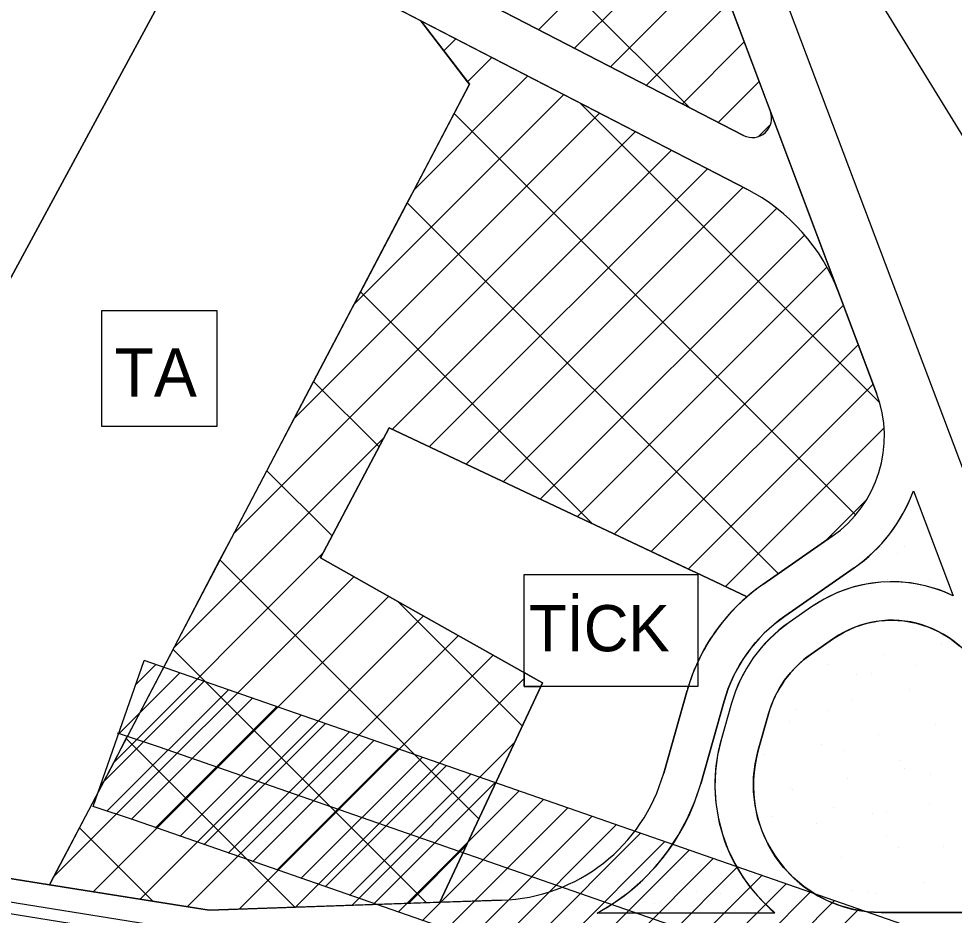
# Model space of a CAD drawing. Extents: x 409341 to 428634, y 4447481 to 4463281.
# Drawn here: x 419431.2 to 419674.1, y 4460066.6 to 4460299.4 of the extents above; entities that cross this region are included whole.
import ezdxf

# ---------------------------------------------------------------- set-up
doc = ezdxf.new("R2010")
doc.units = 0
for name, color, linetype in [('ADA', 7, 'Continuous'), ('ADAKENARI', 7, 'Continuous'), ('Default', 7, 'Continuous'), ('KALDIRIM', 7, 'Continuous'), ('LJ_SEMBOL', 7, 'Continuous'), ('OSB', 7, 'Continuous'), ('PL_AYA_PARK_DINLENME', 7, 'Continuous'), ('PL_K_DEPOLAMA', 7, 'Continuous'), ('PL_K_K_D_K_C_A', 7, 'Continuous'), ('PL_TA_K_TA', 7, 'Continuous'), ('PL_TİCK', 7, 'Continuous'), ('TA_ENH', 7, 'Continuous'), ('TA_ENH_KORUMA', 7, 'Continuous'), ('TA_ENH_TARAMA', 7, 'Continuous'), ('TR_KONUTDISIKCA', 7, 'Continuous'), ('TR_PARKALANI', 7, 'Continuous'), ('TR_TALIISMERK', 7, 'Continuous'), ('TR_TARIM_HAYVANCILIK', 7, 'Continuous'), ('TR_TİCK', 7, 'Continuous')]:
    doc.layers.add(name, color=color, linetype=linetype)

# ---------------------------------------------------------------- blocks, each defined once
blk = doc.blocks.new('POINT_DISPLAY')
at = {"layer": 'Default'}
blk.add_line((0, 0), (0, 0), dxfattribs=at)

msp = doc.modelspace()

# ---------------------------------------------------------------- linework, layer by layer
at = {"layer": 'ADA'}
for p, q in [((419535.64, 4460298.88), (419548.24, 4460282.39)), ((419548.24, 4460282.39), (419439.26, 4460074.5))]:
    msp.add_line(p, q, dxfattribs=at)
at = {"layer": 'ADAKENARI'}
for p, q in [((419536.94, 4460512.57), (419653.98, 4460202.18)), ((419653.98, 4460202.18), (419625.1, 4460278.77)), ((419663.53, 4460176.84), (419673.82, 4460149.56)), ((419642.43, 4460165), (419624.4, 4460152.46)), ((419648.14, 4460156.79), (419630.11, 4460144.25)), ((419637.11, 4460146.68), (419631.25, 4460142.61)), ((419642.82, 4460138.47), (419636.96, 4460134.4)), ((419604.76, 4460124.92), (419598.7, 4460103.49)), ((419614.38, 4460122.19), (419608.32, 4460100.77)), ((419616.31, 4460121.65), (419613.62, 4460112.17)), ((419625.93, 4460118.92), (419623.25, 4460109.45)), ((419439.26, 4460074.5), (419344.65, 4460089.57)), ((419480.72, 4460067.89), (419439.26, 4460074.5)), ((419556.61, 4460070.51), (419480.72, 4460067.89)), ((419581.44, 4460067.18), (419627.56, 4460067.26)), ((419655.17, 4460067.31), (419821.17, 4460067.62))]:
    msp.add_line(p, q, dxfattribs=at)
for points in [[(419475.21, 4460317.39), (419379.85, 4460141.06), (419371.61, 4460146.37), (419358.33, 4460118.38)], [(419476.15, 4460316.98), (419525.99, 4460303.86), (419620.27, 4460255.16)], [(419619.43, 4460269.09), (419530.32, 4460315.13)], [(419619.43, 4460269.09), (419530.32, 4460315.13)], [(419620.34, 4460149.32), (419585.57, 4460165.71), (419553.68, 4460180.75), (419527.39, 4460193.14), (419521.9, 4460182.73), (419509.56, 4460159.37), (419534.24, 4460145.49), (419567.26, 4460126.91), (419540.58, 4460069.96)]]:
    msp.add_lwpolyline(points, dxfattribs=at)
for centre, radius, start, end in [((419621.73, 4460273.53), 5, 242.6779, 20.6604), ((419621.73, 4460273.53), 5, 242.6779, 20.6604), ((419597.32, 4460210.73), 50, 20.6604, 62.678), ((419597.32, 4460210.73), 50, 20.6604, 62.678), ((419624.34, 4460191), 31.67, 304.8245, 20.6604), ((419624.34, 4460191), 41.67, 304.8245, 340.1286), ((419657.92, 4460116.76), 36.45, 64.1379, 124.8245), ((419653.07, 4460111.24), 50.21, 124.8245, 164.1975), ((419653.07, 4460111.24), 40.21, 124.8245, 164.1975), ((419653.07, 4460111.24), 38.21, 124.8245, 164.1975), ((419657.92, 4460116.76), 26.45, 20.6604, 124.8245), ((419653.07, 4460111.24), 28.21, 124.8245, 164.1975), ((419655.11, 4460100.43), 43.11, 164.1975, 230.2869), ((419655.11, 4460100.43), 33.11, 164.1975, 270.1071), ((419555.05, 4460115.84), 45.36, 271.9749, 344.1975), ((419555.05, 4460115.84), 55.36, 298.469, 344.1975)]:
    msp.add_arc(centre, radius, start, end, dxfattribs=at)
at = {"layer": 'KALDIRIM'}
for p, q in [((419719.75, 4460067.43), (419530, 4460570.64)), ((419295.43, 4460091.34), (419469.34, 4460063.63)), ((419394.38, 4460072.54), (419523, 4460052.04))]:
    msp.add_line(p, q, dxfattribs=at)
at = {"layer": 'LJ_SEMBOL'}
msp.add_lwpolyline([(419452.75, 4460193.58), (419482.75, 4460193.58), (419482.75, 4460223.58), (419452.75, 4460223.58)], close=True, dxfattribs=at)
at = {"layer": 'OSB'}
msp.add_lwpolyline([(420374, 4458402.25), (420333.73, 4458554.43), (420007.65, 4459406.75), (419828, 4459907.45), (419873.71, 4459964.63), (419861.99, 4460046.05), (419800.79, 4460096.52), (419788.07, 4460171.32), (419687.29, 4460251.24), (419645.19, 4460319.68), (419562.32, 4460570.29)], dxfattribs=at)
at = {"layer": 'PL_AYA_PARK_DINLENME'}
msp.add_lwpolyline([(419673.82, 4460149.56), (419670.26, 4460151.06), (419666.57, 4460152.17), (419662.78, 4460152.89), (419658.93, 4460153.2), (419655.07, 4460153.1), (419651.25, 4460152.59), (419647.5, 4460151.69), (419643.86, 4460150.39), (419640.39, 4460148.72), (419637.11, 4460146.68), (419631.25, 4460142.61), (419628.64, 4460140.62), (419626.21, 4460138.42), (419623.98, 4460136.01), (419621.96, 4460133.43), (419620.17, 4460130.67), (419618.63, 4460127.78), (419617.33, 4460124.76), (419616.31, 4460121.65), (419613.62, 4460112.17), (419613.62, 4460112.17), (419612.69, 4460108.13), (419612.14, 4460104.03), (419612, 4460099.89), (419612.25, 4460095.75), (419612.89, 4460091.66), (419613.93, 4460087.65), (419615.35, 4460083.76), (419617.13, 4460080.02), (419619.27, 4460076.47), (419621.73, 4460073.14), (419624.5, 4460070.06), (419627.56, 4460067.26), (419581.44, 4460067.18), (419585.64, 4460069.7), (419589.61, 4460072.6), (419593.31, 4460075.83), (419596.7, 4460079.37), (419599.76, 4460083.2), (419602.48, 4460087.29), (419604.82, 4460091.6), (419606.77, 4460096.11), (419608.32, 4460100.77), (419614.38, 4460122.19), (419615.46, 4460125.47), (419616.82, 4460128.65), (419618.45, 4460131.69), (419620.33, 4460134.59), (419622.46, 4460137.31), (419624.8, 4460139.84), (419627.36, 4460142.16), (419630.11, 4460144.25), (419648.14, 4460156.79), (419650.7, 4460158.73), (419653.11, 4460160.85), (419655.34, 4460163.15), (419657.39, 4460165.62), (419659.25, 4460168.24), (419660.9, 4460170.99), (419662.33, 4460173.87), (419663.53, 4460176.84)], close=True, dxfattribs=at)
msp.add_lwpolyline([(419821.17, 4460067.62), (419655.17, 4460067.31), (419651.58, 4460067.5), (419648.02, 4460068.08), (419644.56, 4460069.04), (419641.21, 4460070.37), (419638.03, 4460072.06), (419635.05, 4460074.08), (419632.31, 4460076.41), (419629.84, 4460079.02), (419627.67, 4460081.89), (419625.82, 4460084.98), (419624.31, 4460088.25), (419623.17, 4460091.66), (419622.41, 4460095.18), (419622.04, 4460098.76), (419622.05, 4460102.36), (419622.45, 4460105.94), (419623.25, 4460109.45), (419625.93, 4460118.92), (419626.69, 4460121.23), (419627.64, 4460123.45), (419628.78, 4460125.59), (419630.1, 4460127.62), (419631.59, 4460129.53), (419633.24, 4460131.31), (419635.03, 4460132.93), (419636.96, 4460134.4), (419642.82, 4460138.47), (419645.55, 4460140.14), (419648.47, 4460141.46), (419651.53, 4460142.43), (419654.68, 4460143.01), (419657.87, 4460143.21), (419661.07, 4460143.02), (419664.22, 4460142.45), (419667.28, 4460141.5), (419670.21, 4460140.18), (419672.95, 4460138.53), (419675.47, 4460136.55)], dxfattribs=at)
at = {"layer": 'PL_K_DEPOLAMA'}
msp.add_lwpolyline([(419365.48, 4460150.33), (419371.61, 4460146.37), (419379.85, 4460141.06), (419475.21, 4460317.39)], dxfattribs=at)
at = {"layer": 'PL_K_K_D_K_C_A'}
for points in [[(419626.41, 4460275.3), (419625.1, 4460278.77), (419536.94, 4460512.57), (419511.17, 4460550.76), (419501.92, 4460557.43), (419484.67, 4460569.62), (419475.35, 4460571.21)], [(419524.28, 4460316.72), (419530.32, 4460315.13), (419619.43, 4460269.09)], [(419620.27, 4460255.16), (419535.64, 4460298.88), (419548.24, 4460282.39), (419439.26, 4460074.5), (419480.72, 4460067.89), (419540.58, 4460069.96), (419566.84, 4460126.03), (419562.48, 4460126.03), (419562.48, 4460129.6), (419561.93, 4460129.91), (419534.24, 4460145.49), (419509.56, 4460159.37), (419521.9, 4460182.73), (419527.39, 4460193.14), (419553.68, 4460180.75), (419585.57, 4460165.71), (419605.16, 4460156.48), (419607.05, 4460155.58), (419620.34, 4460149.32)], [(419653.98, 4460202.18), (419644.1, 4460228.38)], [(419624.4, 4460152.46), (419642.43, 4460165)], [(419562.48, 4460128.04), (419562.48, 4460126.03), (419566.84, 4460126.03), (419567.26, 4460126.91), (419566.32, 4460127.44), (419562.48, 4460129.6), (419562.48, 4460128.04)]]:
    msp.add_lwpolyline(points, dxfattribs=at)
for centre, radius, start, end in [((419621.73, 4460273.53), 5, 242.6779, 20.6604), ((419597.32, 4460210.73), 50, 20.6604, 62.678), ((419624.34, 4460191), 31.67, 304.8245, 20.6604), ((419653.07, 4460111.24), 50.21, 124.8245, 130.686)]:
    msp.add_arc(centre, radius, start, end, dxfattribs=at)
at = {"layer": 'PL_TA_K_TA'}
for points in [[(419475.21, 4460317.39), (419379.85, 4460141.06), (419371.61, 4460146.37), (419358.33, 4460118.38)], [(419384.04, 4460083.3), (419439.26, 4460074.5), (419440.4, 4460076.67), (419447, 4460089.26), (419455.98, 4460106.39), (419459.16, 4460112.46), (419459.45, 4460113.01), (419471.32, 4460135.65), (419471.56, 4460136.11), (419483.48, 4460158.85), (419487.14, 4460165.84), (419495.64, 4460182.04), (419502.73, 4460195.56), (419507.8, 4460205.24), (419518.31, 4460225.29), (419519.96, 4460228.44), (419532.12, 4460251.63), (419533.89, 4460255.01), (419544.28, 4460274.83), (419548.24, 4460282.39), (419547.76, 4460283.02), (419541.63, 4460291.04), (419535.64, 4460298.88), (419525.99, 4460303.86)]]:
    msp.add_lwpolyline(points, dxfattribs=at)
at = {"layer": 'PL_TİCK'}
for points in [[(419620.34, 4460149.32), (419607.05, 4460155.58), (419605.16, 4460156.48), (419585.57, 4460165.71), (419553.68, 4460180.75), (419527.39, 4460193.14), (419521.9, 4460182.73), (419509.56, 4460159.37), (419534.24, 4460145.49), (419561.93, 4460129.91), (419566.32, 4460127.44), (419567.26, 4460126.91), (419540.58, 4460069.96), (419556.61, 4460070.51)], [(419598.7, 4460103.49), (419604.76, 4460124.92)]]:
    msp.add_lwpolyline(points, dxfattribs=at)
for centre, radius, start, end in [((419653.07, 4460111.24), 50.21, 130.686, 164.1975), ((419555.05, 4460115.84), 45.36, 271.9749, 344.1975)]:
    msp.add_arc(centre, radius, start, end, dxfattribs=at)
at = {"layer": 'TA_ENH'}
msp.add_lwpolyline([(419893.36, 4459786.57), (419715.35, 4460024.04), (419467.79, 4460110.22), (419456.92, 4460113.85)], dxfattribs=at)
at = {"layer": 'TA_ENH_KORUMA'}
msp.add_line((419450.59, 4460094.88), (419463.79, 4460132.79), dxfattribs=at)
for points in [[(419911.21, 4459796.11), (419727.69, 4460040.92), (419463.79, 4460132.79)], [(419875.52, 4459777.03), (419703.01, 4460007.16), (419461.34, 4460091.29), (419450.59, 4460094.88)]]:
    msp.add_lwpolyline(points, dxfattribs=at)
at = {"layer": 'TA_ENH_TARAMA'}
for p, q in [((419461.61, 4460126.55), (419466.8, 4460131.74)), ((419457.08, 4460113.54), (419473.1, 4460129.55)), ((419452.55, 4460100.52), (419479.39, 4460127.36)), ((419454.15, 4460093.64), (419485.68, 4460125.17)), ((419460.45, 4460091.45), (419491.98, 4460122.98)), ((419466.75, 4460089.26), (419498.27, 4460120.79)), ((419473.05, 4460087.07), (419504.57, 4460118.59)), ((419479.34, 4460084.89), (419510.86, 4460116.4)), ((419485.64, 4460082.7), (419517.16, 4460114.21)), ((419491.94, 4460080.51), (419523.45, 4460112.02)), ((419498.23, 4460078.32), (419529.74, 4460109.83)), ((419504.53, 4460076.13), (419536.04, 4460107.64)), ((419510.83, 4460073.94), (419542.33, 4460105.45)), ((419517.12, 4460071.76), (419548.63, 4460103.26)), ((419523.42, 4460069.57), (419554.92, 4460101.07)), ((419529.72, 4460067.38), (419561.21, 4460098.87)), ((419536.02, 4460065.19), (419567.51, 4460096.68)), ((419542.31, 4460063), (419573.8, 4460094.49)), ((419548.61, 4460060.81), (419580.1, 4460092.3)), ((419554.91, 4460058.63), (419586.39, 4460090.11)), ((419561.2, 4460056.44), (419592.69, 4460087.92)), ((419567.5, 4460054.25), (419598.98, 4460085.73)), ((419573.8, 4460052.06), (419605.27, 4460083.54)), ((419580.09, 4460049.87), (419611.57, 4460081.35)), ((419586.39, 4460047.68), (419617.86, 4460079.15)), ((419592.69, 4460045.5), (419624.16, 4460076.96)), ((419598.99, 4460043.31), (419630.45, 4460074.77)), ((419605.28, 4460041.12), (419636.74, 4460072.58)), ((419611.58, 4460038.93), (419643.04, 4460070.39)), ((419617.88, 4460036.74), (419649.33, 4460068.2))]:
    msp.add_line(p, q, dxfattribs=at)
at = {"layer": 'TR_KONUTDISIKCA'}
for p, q in [((419605.3, 4460276.4), (419534.46, 4460347.24)), ((419566.24, 4460296.57), (419604.11, 4460334.44)), ((419575.56, 4460291.76), (419607.98, 4460324.17)), ((419584.89, 4460286.94), (419611.85, 4460313.9)), ((419594.21, 4460282.12), (419615.72, 4460303.63)), ((419541.63, 4460291.04), (419544.76, 4460294.17)), ((419603.54, 4460277.3), (419619.6, 4460293.36)), ((419547.76, 4460283.02), (419554.08, 4460289.35)), ((419533.89, 4460255.01), (419563.41, 4460284.53)), ((419612.86, 4460272.49), (419623.47, 4460283.09)), ((419518.31, 4460225.29), (419572.73, 4460279.71)), ((419654.73, 4460199.73), (419576.9, 4460277.56)), ((419502.73, 4460195.56), (419582.06, 4460274.9)), ((419648.51, 4460170.59), (419544.28, 4460274.83)), ((419487.14, 4460165.84), (419591.38, 4460270.08)), ((419623.31, 4460268.79), (419626.35, 4460271.84)), ((419528.21, 4460192.76), (419600.71, 4460265.26)), ((419537.82, 4460188.23), (419610.03, 4460260.44)), ((419547.43, 4460183.7), (419619.36, 4460255.63)), ((419628.46, 4460155.29), (419532.12, 4460251.63)), ((419557.04, 4460179.16), (419627.98, 4460250.11)), ((419566.65, 4460174.63), (419635.23, 4460243.22)), ((419576.26, 4460170.1), (419641.04, 4460234.88)), ((419580.11, 4460168.29), (419519.96, 4460228.44)), ((419585.87, 4460165.57), (419645.35, 4460225.05)), ((419595.48, 4460161.04), (419649.23, 4460214.78)), ((419524.8, 4460188.24), (419507.8, 4460205.24)), ((419605.09, 4460156.51), (419653.1, 4460204.51)), ((419614.7, 4460151.98), (419655.84, 4460193.12)), ((419471.56, 4460136.11), (419526.04, 4460190.6)), ((419512.58, 4460165.1), (419495.64, 4460182.04)), ((419640.6, 4460163.73), (419651.08, 4460174.21)), ((419455.98, 4460106.39), (419510.23, 4460160.64)), ((419550.72, 4460091.61), (419483.48, 4460158.85)), ((419440.4, 4460076.67), (419518.23, 4460154.5)), ((419450.57, 4460072.7), (419527.28, 4460149.4)), ((419562, 4460115.68), (419529.57, 4460148.12)), ((419462.77, 4460070.75), (419536.33, 4460144.31)), ((419474.97, 4460068.81), (419545.38, 4460139.22)), ((419537.14, 4460069.84), (419471.32, 4460135.65)), ((419488.46, 4460068.16), (419554.43, 4460134.13)), ((419503.11, 4460068.66), (419562.48, 4460128.04)), ((419502.96, 4460068.66), (419459.16, 4460112.46)), ((419517.75, 4460069.17), (419560, 4460111.42)), ((419466.03, 4460070.23), (419447, 4460089.26)), ((419532.4, 4460069.67), (419547.54, 4460084.82))]:
    msp.add_line(p, q, dxfattribs=at)
at = {"layer": 'TR_TALIISMERK'}
msp.add_lwpolyline([(419562.48, 4460155.06), (419607.6, 4460155.06), (419607.6, 4460126.03), (419562.48, 4460126.03)], close=True, dxfattribs=at)
at = {"layer": 'TR_TARIM_HAYVANCILIK'}
msp.add_lwpolyline([(419365.48, 4460150.33), (419371.61, 4460146.37), (419379.85, 4460141.06), (419475.21, 4460317.39)], dxfattribs=at)
msp.add_lwpolyline([(419365.48, 4460150.33), (419371.61, 4460146.37), (419379.85, 4460141.06), (419475.21, 4460317.39)], dxfattribs=at)
at = {"layer": 'TR_TİCK'}
for points in [[(419620.34, 4460149.32), (419607.05, 4460155.58), (419605.16, 4460156.48), (419585.57, 4460165.71), (419553.68, 4460180.75), (419527.39, 4460193.14), (419521.9, 4460182.73), (419509.56, 4460159.37), (419534.24, 4460145.49), (419561.93, 4460129.91), (419562.48, 4460129.6), (419562.48, 4460155.06), (419607.6, 4460155.06), (419607.6, 4460132.54)], [(419605.09, 4460126.03), (419566.84, 4460126.03), (419540.58, 4460069.96), (419556.61, 4460070.51)], [(419598.7, 4460103.49), (419604.76, 4460124.92)]]:
    msp.add_lwpolyline(points, dxfattribs=at)
for centre, radius, start, end in [((419653.07, 4460111.24), 50.21, 130.686, 154.9052), ((419653.07, 4460111.24), 50.21, 162.8748, 164.1975), ((419555.05, 4460115.84), 45.36, 271.9749, 344.1975)]:
    msp.add_arc(centre, radius, start, end, dxfattribs=at)

# ---------------------------------------------------------------- block references
at = {"layer": 'TR_PARKALANI', "xscale": 0.1, "yscale": 0.10000000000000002}
for p in [(419668.24, 4460163.33), (419659.42, 4460160.54), (419661.1, 4460162.46), (419661.1, 4460162.46), (419656.75, 4460153.69), (419656.75, 4460153.69), (419667.76, 4460153.48), (419667.76, 4460153.48), (419638.22, 4460148.27), (419638.22, 4460148.27), (419670.71, 4460136.82), (419670.71, 4460136.82), (419655.93, 4460134.22), (419655.93, 4460134.22), (419633.98, 4460131.71), (419641.16, 4460131.61), (419641.16, 4460131.61), (419664.39, 4460131.42), (419648.75, 4460129.1), (419652.62, 4460129.35), (419662.59, 4460125.24), (419662.59, 4460125.24), (419647.82, 4460122.63), (419647.82, 4460122.63), (419633.05, 4460120.03), (419633.05, 4460120.03), (419641.13, 4460119.7), (419641.13, 4460119.7), (419631.38, 4460116.93), (419669.25, 4460116.26), (419669.25, 4460116.26), (419613.88, 4460113.51), (419613.88, 4460113.51), (419654.48, 4460113.65), (419654.48, 4460113.65), (419639.71, 4460111.05), (419639.71, 4460111.05), (419645.28, 4460109.41), (419624.94, 4460108.44), (419624.94, 4460108.44), (419660.05, 4460106.8), (419661.14, 4460104.67), (419661.14, 4460104.67), (419646.37, 4460102.07), (419646.37, 4460102.07), (419668.07, 4460103.15), (419631.6, 4460099.46), (419631.6, 4460099.46), (419632.24, 4460099.19), (419667.8, 4460095.69), (419667.8, 4460095.69), (419612.43, 4460092.95), (419612.43, 4460092.95), (419627.04, 4460092.31), (419642.68, 4460094.63), (419653.03, 4460093.09), (419653.03, 4460093.09), (419656.58, 4460093.51), (419656.58, 4460093.51), (419638.26, 4460090.48), (419638.26, 4460090.48), (419656.58, 4460087.1), (419659.69, 4460084.11), (419659.69, 4460084.11), (419671.35, 4460084.5), (419604.32, 4460081.37), (419604.32, 4460081.37), (419644.92, 4460081.5), (419644.92, 4460081.5), (419630.15, 4460078.9), (419630.15, 4460078.9), (419607.09, 4460072.86), (419647.69, 4460072.99), (419666.35, 4460075.13), (419666.35, 4460075.13), (419610.98, 4460072.39), (419610.98, 4460072.39), (419613.38, 4460072.19), (419651.58, 4460072.52), (419651.58, 4460072.52), (419653.98, 4460072.33), (419596.21, 4460069.78), (419596.21, 4460069.78), (419597.74, 4460069.88)]:
    msp.add_blockref('POINT_DISPLAY', p, dxfattribs=at)

# ---------------------------------------------------------------- texts
at = {"layer": 'LJ_SEMBOL'}
msp.add_text('TA', height=12.5, dxfattribs=at).set_placement((419456.13, 4460201.27))
at = {"layer": 'TR_TALIISMERK'}
msp.add_text('TİCK', height=12, dxfattribs=at).set_placement((419563.69, 4460135.14))

doc.saveas('drawing.dxf')
